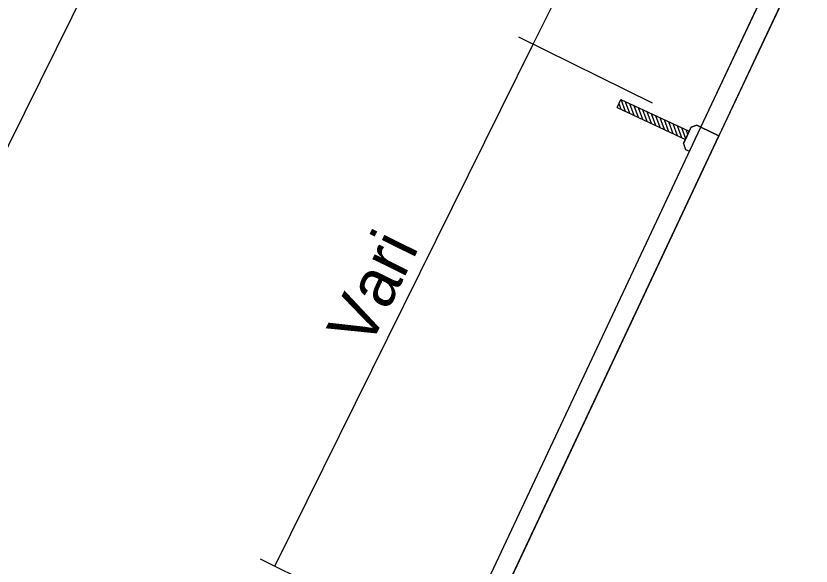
# Model space of a CAD drawing. Extents: x 14104283 to 14121738, y 8635219 to 8671666.
# Drawn here: x 14117674.6 to 14117806.8, y 8668629.1 to 8668720.6 of the extents above; entities that cross this region are included whole.
import ezdxf

# ---------------------------------------------------------------- set-up
doc = ezdxf.new("R2010")
doc.units = 0
for name, color, linetype in [('Cell', 7, 'Continuous'), ('dsnStgShadingPrevPav', 7, 'Continuous'), ('dsnTextFinalPlan', 7, 'Continuous'), ('TC_SubstrataExistingPavement', 7, 'Continuous'), ('Terrain', 7, 'Continuous')]:
    doc.layers.add(name, color=color, linetype=linetype)

msp = doc.modelspace()

# ---------------------------------------------------------------- linework, layer by layer
at = {"layer": 'Cell'}
for p, q in [((14117774.55, 8668705.34), (14117775.18, 8668706.68)), ((14117775.18, 8668706.68), (14117786.52, 8668701.39)), ((14117775.94, 8668704.69), (14117775.23, 8668706.66)), ((14117774.55, 8668705.34), (14117785.89, 8668700.04)), ((14117775.22, 8668705.02), (14117774.86, 8668706.01)), ((14117776.66, 8668704.35), (14117775.94, 8668706.32)), ((14117777.38, 8668704.01), (14117776.66, 8668705.99)), ((14117778.1, 8668703.68), (14117777.38, 8668705.65)), ((14117778.82, 8668703.34), (14117778.1, 8668705.32)), ((14117779.54, 8668703.01), (14117778.82, 8668704.98)), ((14117780.26, 8668702.67), (14117779.54, 8668704.64)), ((14117780.97, 8668702.34), (14117780.26, 8668704.31)), ((14117781.69, 8668702), (14117780.98, 8668703.97)), ((14117782.41, 8668701.67), (14117781.7, 8668703.64)), ((14117783.13, 8668701.33), (14117782.41, 8668703.3)), ((14117783.85, 8668700.99), (14117783.13, 8668702.97)), ((14117784.57, 8668700.66), (14117783.85, 8668702.63)), ((14117787.81, 8668702.42), (14117786.83, 8668702.06)), ((14117786.83, 8668702.06), (14117787.81, 8668702.42)), ((14117788.48, 8668702.11), (14117787.81, 8668702.42)), ((14117787.81, 8668702.42), (14117788.48, 8668702.11)), ((14117785.29, 8668700.32), (14117784.57, 8668702.29)), ((14117785.94, 8668700.16), (14117785.29, 8668701.96)), ((14117785.57, 8668699.37), (14117786.83, 8668702.06)), ((14117786.52, 8668701.39), (14117785.89, 8668700.04)), ((14117786.28, 8668700.88), (14117786.01, 8668701.62)), ((14117786.83, 8668702.06), (14117786.52, 8668701.39)), ((14117786.59, 8668698.08), (14117788.48, 8668702.11)), ((14117786.59, 8668698.08), (14117788.48, 8668702.11)), ((14117785.89, 8668700.04), (14117785.57, 8668699.37)), ((14117785.57, 8668699.37), (14117785.93, 8668698.39)), ((14117785.57, 8668699.37), (14117785.93, 8668698.39)), ((14117785.93, 8668698.39), (14117786.59, 8668698.08)), ((14117785.93, 8668698.39), (14117786.59, 8668698.08))]:
    msp.add_line(p, q, dxfattribs=at)
at = {"layer": 'dsnStgShadingPrevPav'}
for points in [[(14117788.48, 8668702.11), (14117801.31, 8668729.42), (14117804.29, 8668727.94), (14117791.47, 8668700.63)], [(14117747.28, 8668614.41), (14117752.26, 8668625.02), (14117788.48, 8668702.11), (14117791.47, 8668700.63), (14117755.25, 8668623.54), (14117750.26, 8668612.93)]]:
    msp.add_lwpolyline(points, close=True, dxfattribs=at)
at = {"layer": 'dsnTextFinalPlan'}
for p, q in [((14117760.59, 8668715.9), (14117773.96, 8668742.94)), ((14117758.14, 8668717.11), (14117780.37, 8668706.12)), ((14117717.65, 8668629.05), (14117760.59, 8668715.9)), ((14117715.2, 8668630.26), (14117737.43, 8668619.27))]:
    msp.add_line(p, q, dxfattribs=at)
msp.add_lwpolyline([(14117425.32, 8668197.46), (14117939.89, 8669238.2), (14118120.52, 8669148.89), (14117605.96, 8668108.15)], close=True, dxfattribs=at)
at = {"layer": 'TC_SubstrataExistingPavement'}
msp.add_line((14117719.03, 8668546.44), (14117791.47, 8668700.63), dxfattribs=at)
msp.add_lwpolyline([(14117844.93, 8668822.28), (14117847.92, 8668820.81), (14117791.47, 8668700.63), (14117788.48, 8668702.11)], dxfattribs=at)
at = {"layer": 'Terrain'}
for p, q in [((14117788.48, 8668702.11), (14117844.93, 8668822.28)), ((14117716.04, 8668547.92), (14117788.48, 8668702.11))]:
    msp.add_line(p, q, dxfattribs=at)

# ---------------------------------------------------------------- texts
at = {"layer": 'dsnTextFinalPlan'}
msp.add_text('Vari', height=8, rotation=63.6911, dxfattribs=at).set_placement((14117733.23, 8668665.03))

doc.saveas('drawing.dxf')
